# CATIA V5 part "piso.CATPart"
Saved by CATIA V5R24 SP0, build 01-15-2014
Part number: piso
Bounding box of the stored display mesh (mm): x 0 to 3, y -197 to 197, z -197 to 197
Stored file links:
  C:\Users\Fatec\Downloads\Maquina componentes catia\Maquina componentes catia\piso.CATPart
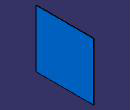
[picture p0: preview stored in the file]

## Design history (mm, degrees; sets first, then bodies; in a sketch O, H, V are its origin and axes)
Body1 (main body)
  Sketch1 on yz-plane, origin (0, 0, 0), H (0, 1, 0), V (0, 0, 1)
    line L1 (-197, 197) -> (197, 197)
    line L2 (197, 197) -> (197, -197)
    line L3 (197, -197) -> (-197, -197)
    line L4 (-197, -197) -> (-197, 197)
    length L3 = 394
    length L4 = 394
    horizontal: L1 H, L3 H
    vertical: L2 V, L4 V
    symmetry: L4 L2 V, L3 L1 H
  Pad1: profile Sketch1, direction (1, 0, 0), length 3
